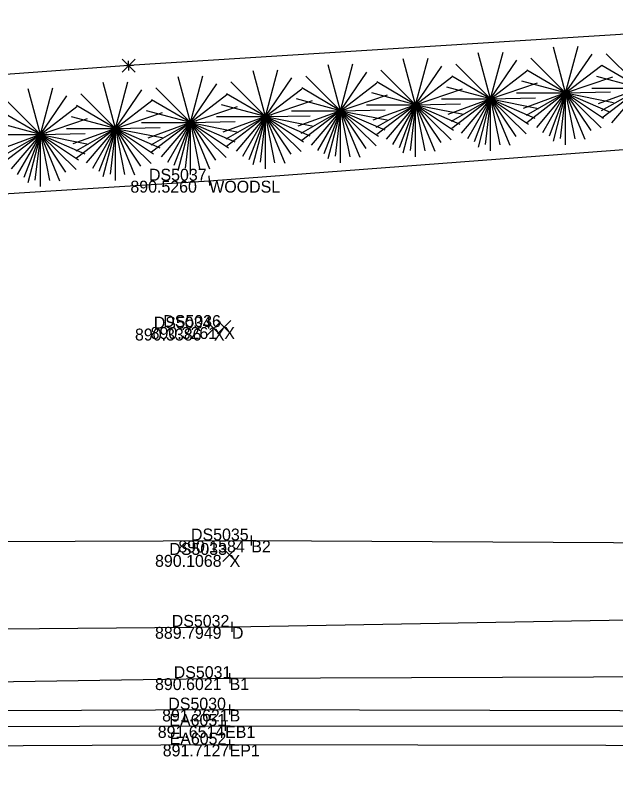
# Model space of a CAD drawing. Extents: x 179044 to 189691, y 286531 to 301257.
# Drawn here: x 179963.1 to 180023.6, y 300591.8 to 300668.9 of the extents above; entities that cross this region are included whole.
import ezdxf

# ---------------------------------------------------------------- set-up
doc = ezdxf.new("R2010")
doc.units = 0
for name, color, linetype in [('DR_X_Ditch', 7, 'Continuous'), ('PV_X_EOP', 7, 'Continuous'), ('PV_X_Shoulder_Aggregate', 7, 'Continuous'), ('RD_X_Fence', 7, 'Continuous'), ('SV_X_Break_Lines', 7, 'Continuous'), ('SV_X_Random_Point', 7, 'Continuous'), ('SV_X_Shot_Marker', 7, 'Continuous'), ('SV_X_Text_Comment', 7, 'Continuous'), ('SV_X_Text_Elevation', 7, 'Continuous'), ('SV_X_Text_Name', 7, 'Continuous'), ('VG_X_Cells', 7, 'Continuous'), ('VG_X_Text', 7, 'Continuous'), ('VG_X_Tree_Line_Rt', 7, 'Continuous')]:
    doc.layers.add(name, color=color, linetype=linetype)

msp = doc.modelspace()

# ---------------------------------------------------------------- linework, layer by layer
at = {"layer": 'DR_X_Ditch'}
msp.add_lwpolyline([(179564.56, 300599.962), (179672.339, 300603.26), (179771.172, 300605.494), (179880.337, 300606.441), (179984.937, 300607.328), (180077.947, 300608.965), (180127.19, 300616.843), (180132.045, 300619.573), (180144.286, 300623.545), (180155.547, 300629.29), (180160.465, 300633.547)], dxfattribs=at)
at = {"layer": 'PV_X_EOP'}
msp.add_lwpolyline([(179370.831, 300591.751), (179475.585, 300592.875), (179659.265, 300594.122), (179770.991, 300594.472), (179880.742, 300594.985), (179984.71, 300595.495), (180079.288, 300595.313), (180129.921, 300597.382), (180139.474, 300598.239), (180154.233, 300602.666), (180170.463, 300611.587), (180179.633, 300620.691), (180184.59, 300626.615), (180188.342, 300633.535), (180190.62, 300639.725), (180171.316, 300693.382), (180137.201, 300785.062), (180098.417, 300888.791)], dxfattribs=at)
at = {"layer": 'PV_X_Shoulder_Aggregate'}
msp.add_lwpolyline([(179563.565, 300594.924), (179658.987, 300595.359), (179770.596, 300596.259), (179881.565, 300597.129), (179984.257, 300597.357), (180079.139, 300597.322), (180129.307, 300600.299), (180139.964, 300601.425), (180153.02, 300605.118), (180169.97, 300613.883), (180177.635, 300623.691), (180181.654, 300635.111), (180182.998, 300649.235), (180167.771, 300692.69), (180134.639, 300784.201), (180095.484, 300888.508)], dxfattribs=at)
at = {"layer": 'RD_X_Fence'}
msp.add_lwpolyline([(180033.616, 300896.161), (180069.423, 300800.637), (180103.118, 300709.458), (180117.129, 300674.9), (180112.616, 300673.011), (180037.359, 300667.77), (179974.547, 300663.799), (179875.902, 300656.609), (179766.558, 300649.439), (179668.068, 300642.7), (179565.54, 300636.358)], dxfattribs=at)
at = {"layer": 'SV_X_Break_Lines'}
for points in [[(179564.638, 300606.986), (179671.768, 300606.922), (179771.087, 300608.912), (179880.599, 300615.611), (179986.884, 300616.02), (180078.033, 300615.521), (180124.742, 300624.492), (180128.289, 300624.221), (180137.303, 300629.118), (180148.459, 300633.708), (180154.503, 300636.496), (180146.307, 300651.241), (180135.969, 300673.811), (180118.542, 300716.074), (180095.911, 300772.35), (180076.611, 300824.96), (180047.5, 300900.199)], [(179564.191, 300598.682), (179770.809, 300601.942), (179880.33, 300600.557), (179984.707, 300602.17), (180076.298, 300602.513), (180129.447, 300605.473), (180133.823, 300610.665), (180143.543, 300612.063), (180154.911, 300619.358), (180168.807, 300625.749), (180172.898, 300631.66), (180174.527, 300641.071), (180168.307, 300660.619), (180157.537, 300688.57), (180123.865, 300779.294), (180087.271, 300883.216)], [(179564.385, 300595.92), (179672.75, 300596.68), (179770.459, 300597.562), (179880.51, 300598.544), (179984.703, 300599.007), (180076.342, 300598.773), (180129.476, 300602.027), (180135.94, 300603.814), (180151.807, 300606.879), (180162.976, 300612.722)]]:
    msp.add_lwpolyline(points, dxfattribs=at)
at = {"layer": 'SV_X_Random_Point'}
for p, q in [((179973.88, 300663.132), (179975.213, 300664.467)), ((179973.88, 300664.467), (179975.213, 300663.132)), ((179982.46, 300636.673), (179983.794, 300638.008)), ((179982.46, 300638.008), (179983.794, 300636.673)), ((179983.5, 300636.829), (179984.833, 300638.165)), ((179983.5, 300638.165), (179984.833, 300636.829)), ((179984.036, 300613.901), (179985.369, 300615.236)), ((179984.036, 300615.236), (179985.369, 300613.901))]:
    msp.add_line(p, q, dxfattribs=at)
at = {"layer": 'SV_X_Shot_Marker'}
for p, q in [((179974.578, 300663.3), (179974.515, 300664.298)), ((179975.046, 300663.831), (179974.048, 300663.768)), ((179974.547, 300663.799), (179974.547, 300663.799)), ((179982.624, 300652.722), (179982.687, 300651.724)), ((179982.156, 300652.191), (179983.154, 300652.254)), ((179982.655, 300652.223), (179982.655, 300652.223)), ((179986.882, 300616.52), (179986.886, 300615.521)), ((179986.384, 300616.019), (179987.384, 300616.022)), ((179986.884, 300616.02), (179986.884, 300616.02)), ((179984.933, 300607.828), (179984.941, 300606.828)), ((179984.437, 300607.324), (179985.437, 300607.332)), ((179984.937, 300607.328), (179984.937, 300607.328)), ((179984.699, 300602.67), (179984.715, 300601.67)), ((179984.207, 300602.162), (179985.207, 300602.178)), ((179984.707, 300602.17), (179984.707, 300602.17)), ((179984.7, 300599.507), (179984.705, 300598.507)), ((179984.203, 300599.004), (179985.203, 300599.009)), ((179984.703, 300599.007), (179984.703, 300599.007)), ((179984.256, 300597.857), (179984.258, 300596.857)), ((179983.757, 300597.356), (179984.757, 300597.358)), ((179984.257, 300597.357), (179984.257, 300597.357)), ((179984.21, 300595.493), (179985.21, 300595.498)), ((179984.708, 300595.995), (179984.713, 300594.995)), ((179984.71, 300595.495), (179984.71, 300595.495))]:
    msp.add_line(p, q, dxfattribs=at)
at = {"layer": 'VG_X_Cells'}
for p, q in [((180018.52, 300661.057), (180017.285, 300665.671)), ((180018.52, 300661.057), (180019.777, 300665.756)), ((180010.968, 300660.461), (180009.733, 300665.075)), ((180010.968, 300660.461), (180012.225, 300665.16)), ((180018.52, 300661.057), (180021.175, 300664.942)), ((180026.082, 300661.519), (180022.592, 300665.005)), ((180003.416, 300659.865), (180002.181, 300664.478)), ((180003.416, 300659.865), (180004.673, 300664.563)), ((180010.968, 300660.461), (180013.623, 300664.346)), ((180018.52, 300661.057), (180015.03, 300664.544)), ((179988.313, 300658.673), (179989.569, 300663.371)), ((179995.865, 300659.269), (179994.63, 300663.882)), ((179995.865, 300659.269), (179997.121, 300663.967)), ((180003.416, 300659.865), (179999.926, 300663.352)), ((180003.416, 300659.865), (180006.071, 300663.75)), ((180010.968, 300660.461), (180007.478, 300663.948)), ((180018.52, 300661.057), (180014.613, 300663.354)), ((180018.52, 300661.057), (180022.177, 300663.862)), ((180026.082, 300661.519), (180022.176, 300663.815)), ((179980.761, 300658.077), (179979.526, 300662.69)), ((179980.761, 300658.077), (179982.018, 300662.775)), ((179988.313, 300658.673), (179987.078, 300663.286)), ((179995.865, 300659.269), (179992.375, 300662.756)), ((179995.865, 300659.269), (179998.52, 300663.154)), ((180003.416, 300659.865), (180007.073, 300662.67)), ((180010.968, 300660.461), (180007.062, 300662.758)), ((180010.968, 300660.461), (180014.625, 300663.266)), ((180018.52, 300661.057), (180023.257, 300662.664)), ((180026.082, 300661.519), (180021.669, 300662.702)), ((179973.209, 300657.48), (179971.974, 300662.094)), ((179973.209, 300657.48), (179974.466, 300662.179)), ((179980.761, 300658.077), (179983.416, 300661.962)), ((179988.313, 300658.673), (179984.823, 300662.159)), ((179988.313, 300658.673), (179990.968, 300662.558)), ((179995.865, 300659.269), (179999.521, 300662.074)), ((180003.416, 300659.865), (179999.51, 300662.162)), ((180010.968, 300660.461), (180015.705, 300662.068)), ((180018.52, 300661.057), (180014.107, 300662.241)), ((179965.658, 300656.87), (179964.423, 300661.483)), ((179965.658, 300656.87), (179966.915, 300661.568)), ((179973.209, 300657.48), (179975.864, 300661.365)), ((179980.761, 300658.077), (179977.271, 300661.563)), ((179988.313, 300658.673), (179991.969, 300661.478)), ((179995.865, 300659.269), (179991.958, 300661.566)), ((180003.416, 300659.865), (179999.003, 300661.048)), ((180003.416, 300659.865), (180008.153, 300661.472)), ((180010.968, 300660.461), (180006.555, 300661.645)), ((180013.585, 300661.057), (180018.52, 300661.057)), ((180018.52, 300661.057), (180014.23, 300659.496)), ((180018.52, 300661.057), (180014.537, 300658.776)), ((180018.52, 300661.057), (180014.613, 300658.062)), ((180018.52, 300661.057), (180015.575, 300657.591)), ((180018.52, 300661.057), (180016.202, 300657.042)), ((180018.52, 300661.057), (180016.855, 300656.717)), ((180018.52, 300661.057), (180017.257, 300656.201)), ((180018.52, 300661.057), (180017.978, 300656.466)), ((180018.52, 300661.057), (180023.03, 300661.149)), ((180018.52, 300655.817), (180018.52, 300661.057)), ((180018.52, 300661.057), (180019.442, 300656.421)), ((180018.52, 300661.057), (180020.453, 300656.389)), ((180018.52, 300661.057), (180021.057, 300657.264)), ((180018.52, 300661.057), (180022.108, 300657.536)), ((180018.52, 300661.057), (180022.342, 300658.502)), ((180018.52, 300661.057), (180022.985, 300659.116)), ((180018.52, 300661.057), (180023.348, 300660.099)), ((180021.147, 300661.519), (180026.082, 300661.519)), ((180026.082, 300661.519), (180021.792, 300659.957)), ((180026.082, 300661.519), (180022.099, 300659.237)), ((180026.082, 300661.519), (180022.176, 300658.524)), ((180026.082, 300661.519), (180023.137, 300658.052)), ((179965.658, 300656.87), (179962.168, 300660.357)), ((179965.658, 300656.87), (179968.313, 300660.755)), ((179973.209, 300657.48), (179969.719, 300660.967)), ((179973.209, 300657.48), (179976.866, 300660.285)), ((179980.761, 300658.077), (179976.854, 300660.373)), ((179980.761, 300658.077), (179984.418, 300660.882)), ((179988.313, 300658.673), (179984.406, 300660.969)), ((179988.313, 300658.673), (179993.049, 300660.279)), ((179995.865, 300659.269), (179991.451, 300660.452)), ((179995.865, 300659.269), (180000.601, 300660.876)), ((180006.033, 300660.461), (180010.968, 300660.461)), ((180010.968, 300660.461), (180006.678, 300658.9)), ((180010.968, 300660.461), (180006.985, 300658.18)), ((180010.968, 300660.461), (180007.062, 300657.466)), ((180010.968, 300660.461), (180008.023, 300656.995)), ((180010.968, 300660.461), (180008.65, 300656.446)), ((180010.968, 300660.461), (180009.303, 300656.121)), ((180010.968, 300660.461), (180009.705, 300655.605)), ((180010.968, 300660.461), (180010.427, 300655.87)), ((180010.968, 300660.461), (180015.478, 300660.553)), ((180010.968, 300655.221), (180010.968, 300660.461)), ((180010.968, 300660.461), (180011.89, 300655.825)), ((180010.968, 300660.461), (180012.902, 300655.793)), ((180010.968, 300660.461), (180013.505, 300656.668)), ((180010.968, 300660.461), (180014.557, 300656.94)), ((180010.968, 300660.461), (180014.79, 300657.906)), ((180010.968, 300660.461), (180015.433, 300658.52)), ((180010.968, 300660.461), (180015.797, 300659.503)), ((179965.658, 300656.87), (179969.315, 300659.675)), ((179973.209, 300657.48), (179969.303, 300659.777)), ((179980.761, 300658.077), (179985.498, 300659.683)), ((179988.313, 300658.673), (179983.899, 300659.856)), ((179998.481, 300659.865), (180003.416, 300659.865)), ((180003.416, 300659.865), (179999.126, 300658.303)), ((180003.416, 300659.865), (179999.433, 300657.583)), ((180003.416, 300659.865), (179999.51, 300656.87)), ((180003.416, 300659.865), (180000.471, 300656.398)), ((180003.416, 300659.865), (180001.098, 300655.85)), ((180003.416, 300659.865), (180001.751, 300655.525)), ((180003.416, 300659.865), (180002.153, 300655.008)), ((180003.416, 300659.865), (180002.875, 300655.273)), ((180003.416, 300659.865), (180007.926, 300659.957)), ((180003.416, 300654.625), (180003.416, 300659.865)), ((180003.416, 300659.865), (180004.338, 300655.228)), ((180003.416, 300659.865), (180005.35, 300655.197)), ((180003.416, 300659.865), (180005.953, 300656.072)), ((180003.416, 300659.865), (180007.005, 300656.343)), ((180003.416, 300659.865), (180007.238, 300657.31)), ((180003.416, 300659.865), (180007.881, 300657.923)), ((180003.416, 300659.865), (180008.245, 300658.907)), ((179965.658, 300656.87), (179961.752, 300659.167)), ((179973.209, 300657.48), (179977.946, 300659.087)), ((179980.761, 300658.077), (179976.348, 300659.26)), ((179988.313, 300658.673), (179992.823, 300658.764)), ((179990.93, 300659.269), (179995.865, 300659.269)), ((179995.865, 300659.269), (179991.575, 300657.707)), ((179995.865, 300659.269), (179991.881, 300656.987)), ((179995.865, 300659.269), (179991.958, 300656.274)), ((179995.865, 300659.269), (179992.92, 300655.802)), ((179995.865, 300659.269), (179993.546, 300655.254)), ((179995.865, 300659.269), (179994.2, 300654.929)), ((179995.865, 300659.269), (179994.601, 300654.412)), ((179995.865, 300659.269), (179995.323, 300654.677)), ((179995.865, 300659.269), (180000.375, 300659.361)), ((179995.865, 300654.029), (179995.865, 300659.269)), ((179995.865, 300659.269), (179996.786, 300654.632)), ((179995.865, 300659.269), (179997.798, 300654.601)), ((179995.865, 300659.269), (179998.401, 300655.476)), ((179995.865, 300659.269), (179999.453, 300655.747)), ((179995.865, 300659.269), (179999.686, 300656.714)), ((179995.865, 300659.269), (180000.33, 300657.327)), ((179995.865, 300659.269), (180000.693, 300658.311)), ((179965.658, 300656.87), (179961.245, 300658.053)), ((179965.658, 300656.87), (179970.395, 300658.477)), ((179973.209, 300657.48), (179968.796, 300658.664)), ((179975.826, 300658.077), (179980.761, 300658.077)), ((179980.761, 300658.077), (179976.471, 300656.515)), ((179980.761, 300658.077), (179976.778, 300655.795)), ((179980.761, 300658.077), (179976.854, 300655.082)), ((179980.761, 300658.077), (179977.816, 300654.61)), ((179980.761, 300658.077), (179978.443, 300654.062)), ((179980.761, 300658.077), (179979.096, 300653.737)), ((179980.761, 300658.077), (179979.498, 300653.22)), ((179980.761, 300658.077), (179980.219, 300653.485)), ((179980.761, 300658.077), (179985.271, 300658.168)), ((179980.761, 300652.837), (179980.761, 300658.077)), ((179980.761, 300658.077), (179981.683, 300653.44)), ((179980.761, 300658.077), (179982.694, 300653.408)), ((179980.761, 300658.077), (179983.298, 300654.283)), ((179980.761, 300658.077), (179984.349, 300654.555)), ((179980.761, 300658.077), (179984.583, 300655.522)), ((179980.761, 300658.077), (179985.226, 300656.135)), ((179980.761, 300658.077), (179985.589, 300657.118)), ((179983.378, 300658.673), (179988.313, 300658.673)), ((179988.313, 300658.673), (179984.023, 300657.111)), ((179988.313, 300658.673), (179984.329, 300656.391)), ((179988.313, 300658.673), (179984.406, 300655.678)), ((179988.313, 300658.673), (179985.368, 300655.206)), ((179988.313, 300658.673), (179985.994, 300654.658)), ((179988.313, 300658.673), (179986.648, 300654.333)), ((179988.313, 300658.673), (179987.049, 300653.816)), ((179988.313, 300658.673), (179987.771, 300654.081)), ((179988.313, 300653.433), (179988.313, 300658.673)), ((179988.313, 300658.673), (179989.234, 300654.036)), ((179988.313, 300658.673), (179990.246, 300654.004)), ((179988.313, 300658.673), (179990.849, 300654.879)), ((179988.313, 300658.673), (179991.901, 300655.151)), ((179988.313, 300658.673), (179992.134, 300656.118)), ((179988.313, 300658.673), (179992.778, 300656.731)), ((179988.313, 300658.673), (179993.141, 300657.714)), ((179968.274, 300657.48), (179973.209, 300657.48)), ((179973.209, 300657.48), (179968.919, 300655.919)), ((179973.209, 300657.48), (179969.226, 300655.199)), ((179973.209, 300657.48), (179969.303, 300654.485)), ((179973.209, 300657.48), (179970.264, 300654.014)), ((179973.209, 300657.48), (179970.891, 300653.465)), ((179973.209, 300657.48), (179971.544, 300653.14)), ((179973.209, 300657.48), (179971.946, 300652.624)), ((179973.209, 300657.48), (179972.668, 300652.889)), ((179973.209, 300657.48), (179977.719, 300657.572)), ((179973.209, 300652.24), (179973.209, 300657.48)), ((179973.209, 300657.48), (179974.131, 300652.844)), ((179973.209, 300657.48), (179975.143, 300652.812)), ((179973.209, 300657.48), (179975.746, 300653.687)), ((179973.209, 300657.48), (179976.798, 300653.959)), ((179973.209, 300657.48), (179977.031, 300654.925)), ((179973.209, 300657.48), (179977.674, 300655.539)), ((179973.209, 300657.48), (179978.038, 300656.522)), ((179960.723, 300656.87), (179965.658, 300656.87)), ((179965.658, 300656.87), (179961.368, 300655.308)), ((179965.658, 300656.87), (179961.675, 300654.588)), ((179965.658, 300656.87), (179961.752, 300653.875)), ((179965.658, 300656.87), (179962.713, 300653.403)), ((179965.658, 300656.87), (179963.34, 300652.855)), ((179965.658, 300656.87), (179963.993, 300652.53)), ((179965.658, 300656.87), (179964.395, 300652.013)), ((179965.658, 300656.87), (179965.117, 300652.278)), ((179965.658, 300656.87), (179970.168, 300656.962)), ((179965.658, 300651.63), (179965.658, 300656.87)), ((179965.658, 300656.87), (179966.58, 300652.233)), ((179965.658, 300656.87), (179967.592, 300652.202)), ((179965.658, 300656.87), (179968.195, 300653.077)), ((179965.658, 300656.87), (179969.247, 300653.348)), ((179965.658, 300656.87), (179969.48, 300654.315)), ((179965.658, 300656.87), (179970.123, 300654.928)), ((179965.658, 300656.87), (179970.487, 300655.912))]:
    msp.add_line(p, q, dxfattribs=at)
at = {"layer": 'VG_X_Tree_Line_Rt'}
msp.add_lwpolyline([(179653.026, 300638.702), (179657.624, 300631.959), (179767.935, 300639.504), (179876.981, 300645.549), (179982.655, 300652.223), (180074.045, 300659.112), (180113.167, 300662.01), (180119.55, 300662.124), (180124.383, 300666.201), (180126.147, 300679.098), (180114.54, 300714.374), (180093.362, 300771.604), (180073.514, 300824.308), (180043.465, 300899.612)], dxfattribs=at)

# ---------------------------------------------------------------- texts
at = {"layer": 'SV_X_Text_Comment'}
for s, height, p in [('X', 0.06, (179974.547, 300663.739)), ('FEN', 0.06, (179974.547, 300663.739)), ('TE', 0.12, (180018.52, 300660.937)), ('TE', 0.12, (180010.968, 300660.341)), ('TE', 0.12, (180003.416, 300659.745)), ('TE', 0.12, (179995.865, 300659.149)), ('TE', 0.12, (179980.761, 300657.957)), ('TE', 0.12, (179988.313, 300658.553)), ('TE', 0.12, (179973.209, 300657.36)), ('TE', 0.12, (179965.658, 300656.75)), ('WOODSL', 1.2, (179982.655, 300651.023)), ('X', 1.2, (179983.127, 300636.141)), ('X', 1.2, (179984.167, 300636.297)), ('B2', 1.2, (179986.884, 300614.82)), ('X', 1.2, (179984.702, 300613.369)), ('D', 1.2, (179984.937, 300606.128)), ('B1', 1.2, (179984.707, 300600.97)), ('B', 1.2, (179984.703, 300597.807)), ('EB1', 1.2, (179984.257, 300596.157)), ('EP1', 1.2, (179984.71, 300594.295))]:
    msp.add_text(s, height=height, dxfattribs=at).set_placement(p)
at = {"layer": 'SV_X_Text_Elevation'}
for s, height, p in [('890.5100', 0.06, (179974.168, 300663.739)), ('890.5100', 0.06, (179974.168, 300663.739)), ('890.5260', 1.2, (179974.719, 300651.023)), ('890.3386', 1.2, (179975.181, 300636.141)), ('890.3261', 1.2, (179976.753, 300636.297)), ('890.1584', 1.2, (179979.534, 300614.82)), ('890.1068', 1.2, (179977.201, 300613.369)), ('889.7949', 1.2, (179977.199, 300606.128)), ('890.6021', 1.2, (179977.198, 300600.97)), ('891.2621', 1.2, (179977.913, 300597.807)), ('891.6514', 1.2, (179977.474, 300596.157)), ('891.7127', 1.2, (179977.975, 300594.295))]:
    msp.add_text(s, height=height, dxfattribs=at).set_placement(p)
at = {"layer": 'SV_X_Text_Name'}
for s, height, p in [('SV5033_1', 0.06, (179974.183, 300663.799)), ('SV5033', 0.06, (179974.242, 300663.799)), ('DS5037', 1.2, (179976.59, 300652.223)), ('DS5036', 1.2, (179978.026, 300637.497)), ('DS5034', 1.2, (179977.071, 300637.341)), ('DS5035', 1.2, (179980.819, 300616.02)), ('DS5033', 1.2, (179978.637, 300614.569)), ('DS5032', 1.2, (179978.881, 300607.328)), ('DS5031', 1.2, (179979.079, 300602.17)), ('DS5030', 1.2, (179978.533, 300599.007)), ('EA6051', 1.2, (179978.638, 300597.357)), ('EA6052', 1.2, (179978.664, 300595.495))]:
    msp.add_text(s, height=height, dxfattribs=at).set_placement(p)
at = {"layer": 'VG_X_Text'}
for p in [(180018.52, 300661.057), (180010.968, 300660.461), (180003.416, 300659.865), (179988.313, 300658.673), (179995.865, 300659.269), (179980.761, 300658.077), (179973.209, 300657.48), (179965.658, 300656.87)]:
    msp.add_text(' NOTE:8', height=0.12, dxfattribs=at).set_placement(p)

doc.saveas('drawing.dxf')
